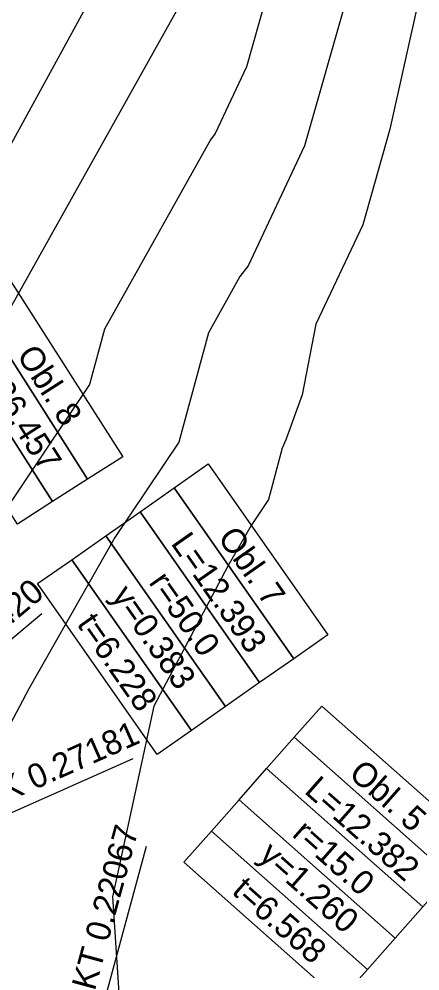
# Model space of a CAD drawing. Extents: x -549394 to -546608, y -1037055 to -1033629.
# Drawn here: x -547807.4 to -547749.6, y -1034715 to -1034578.2 of the extents above; entities that cross this region are included whole.
import ezdxf

# ---------------------------------------------------------------- set-up
doc = ezdxf.new("R2010")
doc.units = 0
for name, color, linetype in [('hlavni_vrst', 7, 'Continuous'), ('norm_vrst', 7, 'Continuous'), ('x_popis_oblouky_C21', 7, 'Continuous')]:
    doc.layers.add(name, color=color, linetype=linetype)

msp = doc.modelspace()

# ---------------------------------------------------------------- linework, layer by layer
at = {"layer": 'hlavni_vrst'}
for p, q in [((-547769.61, -1034567.38), (-547774.62, -1034585.07)), ((-547774.62, -1034585.07), (-547779.14, -1034594.65)), ((-547779.8, -1034595.52), (-547795.06, -1034622.76)), ((-547779.14, -1034594.65), (-547779.8, -1034595.52)), ((-547795.06, -1034622.76), (-547797.21, -1034630.7)), ((-547797.21, -1034630.7), (-547813.16, -1034654.45))]:
    msp.add_line(p, q, dxfattribs=at)
at = {"layer": 'norm_vrst'}
for p, q in [((-547747.51, -1034564.96), (-547753.98, -1034594)), ((-547758.41, -1034568.77), (-547766.25, -1034596.41)), ((-547795.76, -1034572.88), (-547811.34, -1034601.27)), ((-547784.03, -1034575.82), (-547810.04, -1034622.26)), ((-547753.98, -1034594), (-547757.88, -1034607.75)), ((-547766.25, -1034596.41), (-547774.38, -1034613.65)), ((-547757.88, -1034607.75), (-547764.62, -1034622.04)), ((-547774.38, -1034613.65), (-547775.57, -1034615.21)), ((-547775.57, -1034615.21), (-547780.08, -1034623.27)), ((-547764.62, -1034622.04), (-547766.61, -1034632.23)), ((-547780.08, -1034623.27), (-547784.33, -1034638.99)), ((-547766.61, -1034632.23), (-547768.96, -1034638.67)), ((-547784.33, -1034638.99), (-547793.55, -1034652.72)), ((-547768.96, -1034638.67), (-547769.46, -1034639.88)), ((-547769.46, -1034639.88), (-547771.45, -1034647.27)), ((-547771.45, -1034647.27), (-547773.94, -1034650.98)), ((-547773.94, -1034650.98), (-547777.29, -1034656.86)), ((-547793.55, -1034652.72), (-547805.95, -1034674.5)), ((-547777.29, -1034656.86), (-547787.97, -1034676.96)), ((-547805.95, -1034674.5), (-547818.05, -1034697.26)), ((-547787.97, -1034676.96), (-547793.92, -1034704.37)), ((-547793.92, -1034704.37), (-547792.45, -1034725.58))]:
    msp.add_line(p, q, dxfattribs=at)
at = {"layer": 'x_popis_oblouky_C21'}
for points in [[(-547808.58, -1034615.83), (-547792.42, -1034641.1), (-547797.48, -1034644.33), (-547813.64, -1034619.06)], [(-547813.64, -1034619.06), (-547797.48, -1034644.33), (-547802.53, -1034647.56), (-547818.69, -1034622.29)], [(-547818.69, -1034622.29), (-547802.53, -1034647.56), (-547807.59, -1034650.8), (-547823.75, -1034625.52)], [(-547780.11, -1034642.13), (-547762.89, -1034666.69), (-547767.81, -1034670.14), (-547785.03, -1034645.57)], [(-547785.03, -1034645.57), (-547767.81, -1034670.14), (-547772.72, -1034673.58), (-547789.94, -1034649.02)], [(-547789.94, -1034649.02), (-547772.72, -1034673.58), (-547777.63, -1034677.03), (-547794.85, -1034652.46)], [(-547794.85, -1034652.46), (-547777.63, -1034677.03), (-547782.55, -1034680.47), (-547799.77, -1034655.91)], [(-547799.77, -1034655.91), (-547782.55, -1034680.47), (-547787.46, -1034683.92), (-547804.68, -1034659.35)], [(-547763.75, -1034676.96), (-547741.29, -1034696.85), (-547745.27, -1034701.34), (-547767.73, -1034681.45)], [(-547767.73, -1034681.45), (-547745.27, -1034701.34), (-547749.25, -1034705.83), (-547771.71, -1034685.95)], [(-547771.71, -1034685.95), (-547749.25, -1034705.83), (-547753.22, -1034710.32), (-547775.69, -1034690.44)], [(-547775.69, -1034690.44), (-547753.22, -1034710.32), (-547757.2, -1034714.82), (-547779.66, -1034694.93)], [(-547779.66, -1034694.93), (-547757.2, -1034714.82), (-547761.18, -1034719.31), (-547783.64, -1034699.42)]]:
    msp.add_lwpolyline(points, close=True, dxfattribs=at)
for points in [[(-547804.05, -1034663.69), (-547837.73, -1034691.94)], [(-547790.95, -1034684.53), (-547831.12, -1034702.38)], [(-547789.06, -1034697.13), (-547800.59, -1034739.55)]]:
    msp.add_lwpolyline(points, dxfattribs=at)

# ---------------------------------------------------------------- texts
for s, rotation, p in [('L=26.457', 302.6197, (-547814.56, -1034627.01)), ('Obl. 8', 302.6197, (-547807.77, -1034626.48)), ('Obl. 7', 305.0535, (-547778.85, -1034652.74)), ('L=12.393', 305.0535, (-547785.6, -1034653.56)), ('r=50.0', 305.0535, (-547788.77, -1034659.19)), ('KT 0.28420', 39.9916, (-547822.04, -1034676.61)), ('y=0.383', 305.0535, (-547794.19, -1034661.14)), ('t=6.228', 305.0535, (-547799.13, -1034665.17)), ('TK 0.27181', 23.9597, (-547811.84, -1034692)), ('Obl. 5', 318.5051, (-547760.06, -1034686.98)), ('L=12.382', 318.5051, (-547766.44, -1034689.35)), ('KT 0.22067', 74.8025, (-547796.45, -1034718.01)), ('r=15.0', 318.5051, (-547768.2, -1034695.57)), ('y=1.260', 318.5051, (-547773.02, -1034698.73)), ('t=6.568', 318.5051, (-547776.88, -1034703.79))]:
    msp.add_text(s, height=3.5, rotation=rotation, dxfattribs=at).set_placement(p)

doc.saveas('drawing.dxf')
